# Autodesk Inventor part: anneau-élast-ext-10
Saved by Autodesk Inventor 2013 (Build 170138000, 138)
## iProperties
Created: 2012-12
Part Number: anneau-élast-ext-10
Material: Générique
Document SubType Name: Modeling
Designer: jost thierry
Density: 1 g/cm^3
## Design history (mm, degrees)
node "anneau-élast-ext-101"
node "anneau-élast-ext-10"
node "Base1"
